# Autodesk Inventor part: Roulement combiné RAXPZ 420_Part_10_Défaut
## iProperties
Shininess: 64.0
Length Units: 11269
Angle Units: 11279
Time Units: 11290
Mass Units: 11283
Length Display Precision: 3
Angle Display Precision: 2
Compacted: True
Part Number: Roulement combiné RAXPZ 420_Part_10_Défaut
Document SubType Name: Modeling
Created: 2006-01
Material: Par défaut
Designer: riri
Density: 0.0
Volumn: 0.0
Area: 0.0
PropertySet Name: Model Information
Control State: 0
Master: False
Checked Out: False
Author: riri
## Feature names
1. Base1
